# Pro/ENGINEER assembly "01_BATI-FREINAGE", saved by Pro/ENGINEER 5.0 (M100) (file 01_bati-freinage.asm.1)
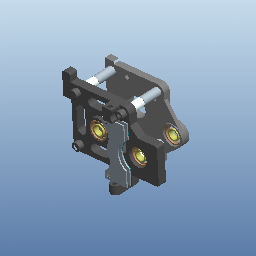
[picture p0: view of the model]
Units: millimeter Newton Second (mmNs); MM, TONNE, HOURS

Other components: E_FLASQUE-GAUCHE, E_FLASQUE-DROIT, VIS_CHC_M-6X40, VIS_CHC_M-6X40, VIS_CHC_M-6X40, 9-PLAQUETTE_FREIN, 9-PLAQUETTE_FREIN

Other named items: A-DROITE, A-DESSUS, A-FACE, A-R0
